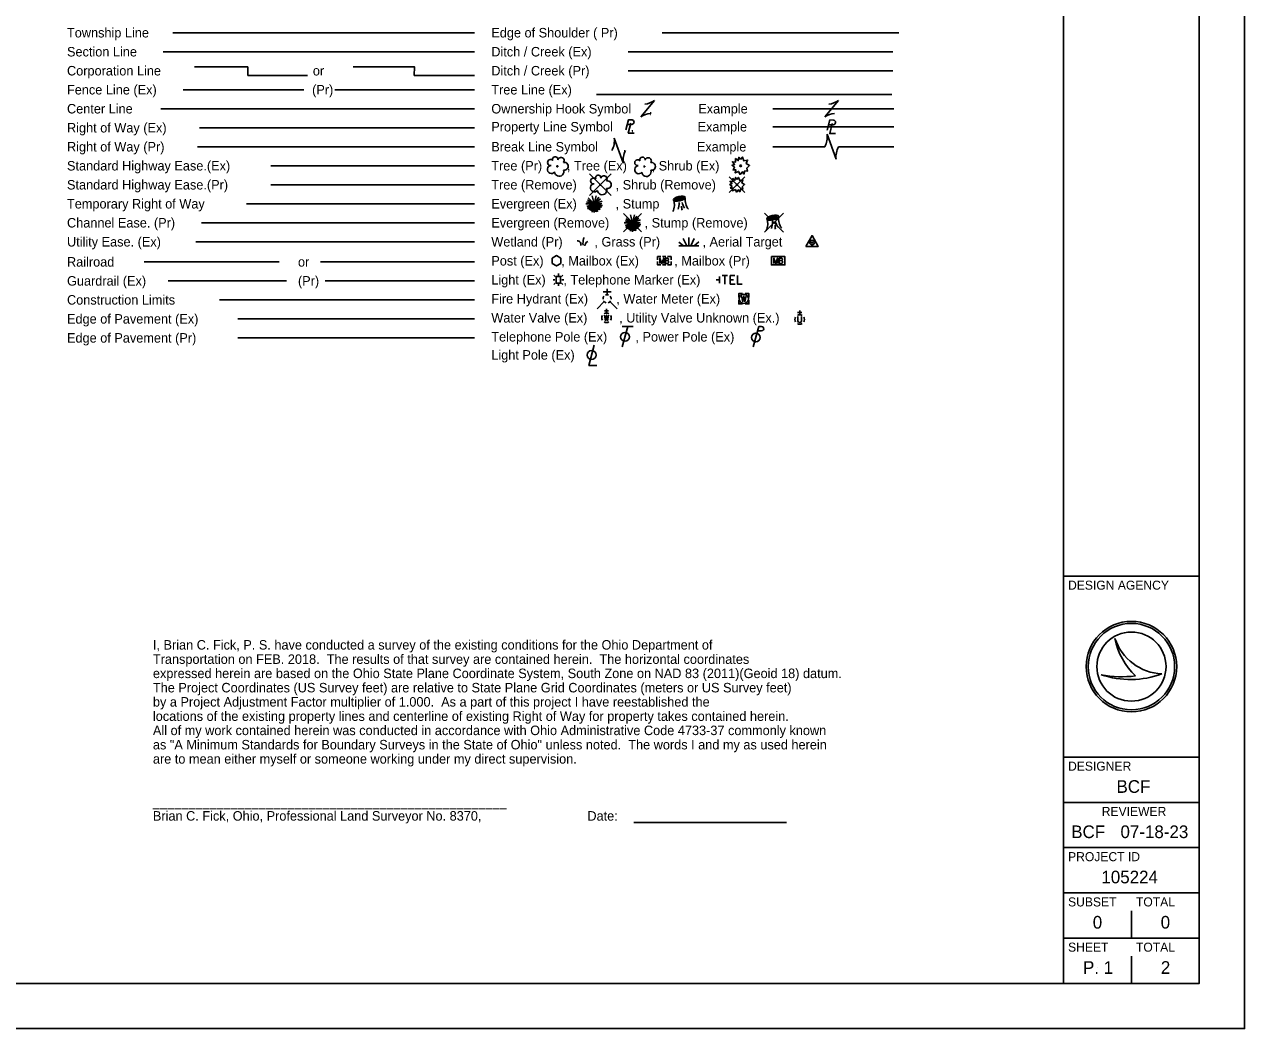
# Model space of a CAD drawing. Extents: x 0 to 1052, y -194 to 246.
# Drawn here: x 20.52 to 34, y 0 to 11.1 of the extents above; entities that cross this region are included whole.
import ezdxf

# ---------------------------------------------------------------- set-up
doc = ezdxf.new("R2010")
doc.units = 0
for name, color, linetype in [('SH_Border', 7, 'Continuous'), ('SH_Cut_Line', 7, 'Continuous'), ('SH_Data', 7, 'Continuous'), ('SH_Text', 7, 'Continuous')]:
    doc.layers.add(name, color=color, linetype=linetype)

msp = doc.modelspace()

# ---------------------------------------------------------------- linework, layer by layer
at = {"layer": 'SH_Border'}
for p, q in [((32, 0.5), (32, 21.5)), ((32, 5), (33.5, 5)), ((32, 3), (33.5, 3)), ((32, 2.5), (33.5, 2.5)), ((32, 2), (33.5, 2)), ((32, 1.5), (33.5, 1.5)), ((32, 1), (33.5, 1))]:
    msp.add_line(p, q, dxfattribs=at)
msp.add_lwpolyline([(1.5, 21.5), (33.5, 21.5), (33.5, 0.5), (1.5, 0.5)], close=True, dxfattribs=at)
at = {"layer": 'SH_Cut_Line'}
msp.add_lwpolyline([(0, 0), (34, 0), (34, 22), (0, 22)], close=True, dxfattribs=at)
at = {"layer": 'SH_Data'}
for p, q in [((32.567, 4.31), (32.567, 4.31)), ((32.417, 3.91), (32.417, 3.91)), ((32.75, 4), (32.75, 4)), ((33.087, 3.919), (33.087, 3.919)), ((32.75, 1), (32.75, 1.3)), ((32.375, 0.675), (32.375, 0.675)), ((32.75, 0.5), (32.75, 0.8))]:
    msp.add_line(p, q, dxfattribs=at)
for radius in [0.5, 0.477, 0.477, 0.382]:
    msp.add_circle((32.75, 4), radius, dxfattribs=at)
for centre, radius, start, end in [((33.116, 4.498), 0.58, 198.9257, 198.9319), ((33.347, 4.47), 0.796, 191.6379, 191.6421), ((33.116, 4.498), 0.58, 198.9319, 267.1657), ((33.347, 4.47), 0.796, 191.6421, 226.0947), ((32.739, 4.87), 1.013, 251.4576, 290.0832), ((32.648, 5.154), 1.266, 259.4964, 259.4995), ((32.739, 4.87), 1.013, 251.4527, 251.4576), ((32.648, 5.154), 1.266, 259.4995, 276.6672)]:
    msp.add_arc(centre, radius, start, end, dxfattribs=at)
at = {"layer": 'SH_Text'}
for p, q in [((22.161, 11.004), (25.492, 11.004)), ((27.567, 11.004), (30.179, 11.004)), ((22.054, 10.794), (25.492, 10.794)), ((27.191, 10.794), (30.116, 10.794)), ((22.402, 10.627), (22.989, 10.627)), ((22.989, 10.627), (22.989, 10.532)), ((22.989, 10.532), (23.65, 10.532)), ((27.191, 10.584), (30.116, 10.584)), ((22.277, 10.374), (23.607, 10.374)), ((23.949, 10.374), (25.492, 10.374)), ((26.841, 10.322), (30.103, 10.322)), ((27.332, 10.074), (27.482, 10.254)), ((29.363, 10.074), (29.513, 10.254)), ((22.028, 10.164), (25.492, 10.164)), ((27.407, 10.164), (27.407, 10.164)), ((28.789, 10.164), (30.126, 10.164)), ((29.438, 10.164), (29.438, 10.164)), ((27.182, 9.991), (27.231, 9.991)), ((29.406, 9.988), (29.455, 9.988)), ((22.454, 9.954), (25.492, 9.954)), ((27.037, 9.841), (27.135, 9.565)), ((27.212, 9.968), (27.212, 9.968)), ((28.789, 9.966), (30.126, 9.966)), ((29.389, 9.883), (29.487, 9.606)), ((29.436, 9.965), (29.436, 9.965)), ((22.433, 9.744), (25.492, 9.744)), ((28.789, 9.744), (29.363, 9.744)), ((29.438, 9.744), (29.438, 9.744)), ((29.513, 9.744), (30.126, 9.744)), ((27.086, 9.703), (27.086, 9.703)), ((23.242, 9.534), (25.492, 9.534)), ((26.762, 9.445), (27.003, 9.204)), ((27.003, 9.445), (26.762, 9.204)), ((23.242, 9.324), (25.492, 9.324)), ((26.882, 9.324), (26.882, 9.324)), ((28.306, 9.411), (28.48, 9.237)), ((28.48, 9.411), (28.306, 9.237)), ((28.393, 9.324), (28.393, 9.324)), ((26.815, 9.114), (26.75, 9.18)), ((26.815, 9.114), (26.792, 9.201)), ((26.815, 9.114), (26.839, 9.202)), ((26.815, 9.114), (26.865, 9.187)), ((26.815, 9.114), (26.884, 9.167)), ((22.976, 9.114), (25.492, 9.114)), ((26.723, 9.114), (26.815, 9.114)), ((26.815, 9.114), (26.732, 9.136)), ((26.815, 9.114), (26.735, 9.085)), ((26.815, 9.114), (26.741, 9.071)), ((26.815, 9.114), (26.742, 9.157)), ((26.815, 9.114), (26.742, 9.058)), ((26.815, 9.114), (26.76, 9.049)), ((26.815, 9.114), (26.772, 9.039)), ((26.815, 9.114), (26.784, 9.033)), ((26.815, 9.114), (26.792, 9.023)), ((26.815, 9.114), (26.805, 9.028)), ((26.815, 9.114), (26.904, 9.144)), ((26.815, 9.114), (26.9, 9.116)), ((26.815, 9.016), (26.815, 9.114)), ((26.815, 9.114), (26.833, 9.027)), ((26.815, 9.114), (26.851, 9.027)), ((26.815, 9.114), (26.863, 9.043)), ((26.815, 9.114), (26.883, 9.048)), ((26.815, 9.114), (26.887, 9.066)), ((26.815, 9.114), (26.899, 9.078)), ((26.815, 9.114), (26.906, 9.096)), ((27.77, 9.114), (27.77, 9.114)), ((22.479, 8.904), (25.492, 8.904)), ((27.138, 9.005), (27.339, 8.804)), ((27.339, 9.005), (27.138, 8.804)), ((27.146, 8.904), (27.238, 8.904)), ((27.238, 8.904), (27.156, 8.927)), ((27.238, 8.904), (27.158, 8.875)), ((27.238, 8.904), (27.164, 8.862)), ((27.238, 8.904), (27.165, 8.947)), ((27.238, 8.904), (27.165, 8.848)), ((27.238, 8.904), (27.173, 8.97)), ((27.238, 8.904), (27.183, 8.839)), ((27.238, 8.904), (27.195, 8.829)), ((27.238, 8.904), (27.207, 8.823)), ((27.238, 8.904), (27.215, 8.991)), ((27.238, 8.904), (27.215, 8.813)), ((27.238, 8.904), (27.228, 8.818)), ((27.238, 8.904), (27.262, 8.992)), ((27.238, 8.904), (27.288, 8.977)), ((27.238, 8.904), (27.307, 8.957)), ((27.238, 8.904), (27.327, 8.935)), ((27.238, 8.904), (27.323, 8.906)), ((27.238, 8.806), (27.238, 8.904)), ((27.238, 8.904), (27.256, 8.817)), ((27.238, 8.904), (27.275, 8.817)), ((27.238, 8.904), (27.286, 8.833)), ((27.238, 8.904), (27.306, 8.838)), ((27.238, 8.904), (27.31, 8.856)), ((27.238, 8.904), (27.322, 8.868)), ((27.238, 8.904), (27.329, 8.886)), ((27.238, 8.904), (27.238, 8.904)), ((28.698, 9.009), (28.906, 8.8)), ((28.906, 9.009), (28.698, 8.8)), ((28.802, 8.904), (28.802, 8.904)), ((28.802, 8.904), (28.802, 8.904)), ((22.416, 8.694), (25.492, 8.694)), ((27.803, 8.649), (27.752, 8.691)), ((27.752, 8.648), (27.972, 8.651)), ((27.839, 8.649), (27.8, 8.729)), ((27.862, 8.649), (27.861, 8.743)), ((27.884, 8.65), (27.921, 8.73)), ((27.921, 8.65), (27.971, 8.695)), ((27.57, 8.53), (27.608, 8.53)), ((21.845, 8.473), (23.335, 8.473)), ((23.792, 8.473), (25.492, 8.473)), ((27.57, 8.439), (27.608, 8.439)), ((27.59, 8.484), (27.59, 8.484)), ((28.848, 8.484), (28.848, 8.484)), ((22.111, 8.263), (23.418, 8.263)), ((23.845, 8.263), (25.492, 8.263)), ((26.381, 8.275), (26.361, 8.275)), ((26.384, 8.311), (26.37, 8.325)), ((26.384, 8.238), (26.37, 8.224)), ((26.42, 8.322), (26.42, 8.342)), ((26.42, 8.274), (26.42, 8.274)), ((26.42, 8.226), (26.42, 8.206)), ((26.47, 8.325), (26.456, 8.311)), ((26.47, 8.224), (26.456, 8.238)), ((26.479, 8.275), (26.459, 8.275)), ((28.199, 8.274), (28.162, 8.274)), ((28.199, 8.237), (28.199, 8.312)), ((27.003, 8.142), (26.913, 8.142)), ((26.958, 8.11), (26.958, 8.174)), ((22.675, 8.053), (25.492, 8.053)), ((26.927, 8.033), (26.849, 7.955)), ((26.952, 7.907), (26.952, 7.955)), ((26.958, 8.064), (26.958, 8.064)), ((26.958, 8.064), (26.958, 8.064)), ((26.99, 8.033), (27.068, 7.955)), ((28.469, 8.064), (28.469, 8.064)), ((22.879, 7.843), (25.492, 7.843)), ((26.975, 7.931), (26.928, 7.931)), ((26.952, 7.854), (26.952, 7.854)), ((29.11, 7.911), (29.062, 7.911)), ((29.066, 7.867), (29.066, 7.815)), ((29.086, 7.887), (29.086, 7.935)), ((29.086, 7.835), (29.086, 7.835)), ((29.106, 7.867), (29.106, 7.815)), ((27.246, 7.757), (27.126, 7.757)), ((27.186, 7.757), (27.126, 7.532)), ((28.633, 7.757), (28.573, 7.532)), ((28.62, 7.709), (28.665, 7.709)), ((28.633, 7.757), (28.665, 7.757)), ((22.879, 7.633), (25.492, 7.633)), ((27.255, 2.278), (28.941, 2.278))]:
    msp.add_line(p, q, dxfattribs=at)
for points in [[(24.154, 10.627), (24.832, 10.627), (24.827, 10.532), (25.492, 10.532)], [(27.166, 9.931), (27.196, 10.043), (27.234, 10.043)], [(27.222, 10.004), (27.192, 9.893), (27.258, 9.893)], [(29.39, 9.928), (29.42, 10.04), (29.459, 10.039)], [(29.446, 10.001), (29.417, 9.89), (29.482, 9.89)], [(28.43, 9.602), (28.453, 9.63), (28.468, 9.59), (28.509, 9.597), (28.496, 9.559), (28.532, 9.537), (28.5, 9.509), (28.509, 9.475), (28.481, 9.478), (28.469, 9.443), (28.453, 9.469), (28.427, 9.439), (28.411, 9.472), (28.373, 9.456), (28.38, 9.491), (28.35, 9.488), (28.367, 9.518), (28.339, 9.539), (28.366, 9.549), (28.343, 9.579), (28.378, 9.575), (28.377, 9.614), (28.406, 9.592), (28.413, 9.629), (28.43, 9.602)], [(28.391, 9.382), (28.41, 9.405), (28.423, 9.372), (28.458, 9.378), (28.447, 9.345), (28.477, 9.326), (28.45, 9.303), (28.458, 9.274), (28.434, 9.276), (28.424, 9.247), (28.41, 9.269), (28.388, 9.243), (28.375, 9.271), (28.342, 9.258), (28.348, 9.288), (28.322, 9.285), (28.337, 9.31), (28.313, 9.328), (28.337, 9.337), (28.317, 9.362), (28.347, 9.359), (28.346, 9.392), (28.37, 9.374), (28.377, 9.405), (28.391, 9.382)], [(26.35, 8.456), (26.399, 8.428), (26.447, 8.456), (26.447, 8.513), (26.399, 8.541), (26.35, 8.513), (26.35, 8.456)], [(27.515, 8.494), (27.515, 8.53), (27.551, 8.53)], [(27.541, 8.454), (27.541, 8.514), (27.563, 8.454), (27.583, 8.514), (27.583, 8.454)], [(27.628, 8.487), (27.63, 8.489), (27.632, 8.491), (27.633, 8.492), (27.633, 8.493), (27.634, 8.495), (27.634, 8.496), (27.635, 8.5), (27.635, 8.501), (27.635, 8.503), (27.635, 8.506), (27.634, 8.508), (27.633, 8.51), (27.63, 8.512), (27.628, 8.513), (27.627, 8.513), (27.625, 8.514), (27.602, 8.514), (27.602, 8.454), (27.628, 8.454), (27.631, 8.456), (27.634, 8.459), (27.636, 8.462), (27.638, 8.467), (27.638, 8.471), (27.638, 8.474), (27.637, 8.477), (27.635, 8.481), (27.633, 8.484), (27.628, 8.487), (27.602, 8.487)], [(27.627, 8.53), (27.665, 8.53), (27.665, 8.494)], [(28.8, 8.454), (28.8, 8.514), (28.821, 8.454), (28.842, 8.514), (28.842, 8.454)], [(28.886, 8.487), (28.889, 8.489), (28.89, 8.491), (28.891, 8.492), (28.892, 8.493), (28.893, 8.495), (28.893, 8.496), (28.894, 8.5), (28.894, 8.501), (28.894, 8.503), (28.894, 8.506), (28.893, 8.508), (28.891, 8.51), (28.889, 8.512), (28.887, 8.513), (28.886, 8.513), (28.884, 8.514), (28.86, 8.514), (28.86, 8.454), (28.886, 8.454), (28.89, 8.456), (28.893, 8.459), (28.895, 8.462), (28.896, 8.467), (28.897, 8.471), (28.897, 8.474), (28.896, 8.477), (28.894, 8.481), (28.892, 8.484), (28.886, 8.487), (28.86, 8.487)], [(27.551, 8.439), (27.515, 8.439), (27.515, 8.475)], [(27.665, 8.475), (27.665, 8.439), (27.627, 8.439)], [(28.23, 8.321), (28.288, 8.321)], [(28.259, 8.321), (28.259, 8.227)], [(28.369, 8.321), (28.318, 8.321), (28.318, 8.227), (28.372, 8.227)], [(28.318, 8.274), (28.354, 8.274)], [(28.398, 8.321), (28.398, 8.227), (28.449, 8.227)], [(28.454, 8.121), (28.412, 8.121), (28.412, 8.079)], [(28.444, 8.098), (28.456, 8.031), (28.469, 8.098), (28.481, 8.031), (28.494, 8.098)], [(28.525, 8.079), (28.525, 8.121), (28.484, 8.121)], [(28.412, 8.049), (28.412, 8.008), (28.454, 8.008)], [(28.484, 8.008), (28.525, 8.008), (28.525, 8.049)], [(26.928, 7.885), (26.94, 7.821), (26.952, 7.885), (26.964, 7.821), (26.975, 7.885)], [(26.817, 7.553), (26.758, 7.329), (26.846, 7.329)]]:
    msp.add_lwpolyline(points, dxfattribs=at)
for points in [[(29.154, 8.642), (29.289, 8.642), (29.222, 8.763)], [(28.773, 8.53), (28.923, 8.53), (28.923, 8.439), (28.773, 8.439)], [(26.395, 8.237), (26.445, 8.237), (26.445, 8.312), (26.395, 8.312)]]:
    msp.add_lwpolyline(points, close=True, dxfattribs=at)
for centre, radius in [((26.408, 9.528), 0.0063), ((27.371, 9.526), 0.0054), ((28.433, 9.534), 0.00864), ((26.882, 9.324), 0.0054), ((28.393, 9.324), 0.00734), ((29.222, 8.685), 0.0263), ((29.222, 8.685), 0.006), ((28.469, 8.064), 0.0506), ((27.156, 7.644), 0.0488), ((28.601, 7.637), 0.0488), ((26.787, 7.443), 0.0488)]:
    msp.add_circle(centre, radius, dxfattribs=at)
for centre, radius, start, end in [((27.363, 10.416), 0.2, 273.6945, 306.337), ((29.394, 10.416), 0.2, 273.6945, 306.337), ((27.45, 9.913), 0.2, 93.6945, 126.337), ((29.482, 9.913), 0.2, 93.6945, 126.337), ((27.23, 10.017), 0.0259, 270.471, 81.3281), ((29.455, 10.014), 0.0259, 270.471, 81.3281), ((26.789, 9.816), 0.25, 332.9422, 5.5848), ((29.14, 9.858), 0.25, 332.9422, 5.5848), ((29.736, 9.631), 0.25, 152.9422, 185.5848), ((26.333, 9.57), 0.0331, 39.0625, 279.5412), ((26.385, 9.604), 0.0296, 354.0047, 205.9741), ((26.449, 9.592), 0.0349, 323.83, 165.0376), ((26.485, 9.529), 0.0431, 259.1453, 101.4596), ((27.384, 9.589), 0.25, 152.9422, 185.5848), ((27.297, 9.568), 0.0331, 39.0625, 279.5412), ((27.349, 9.601), 0.0296, 354.0047, 205.9741), ((27.412, 9.589), 0.0349, 323.83, 165.0376), ((26.343, 9.493), 0.0444, 96.1722, 320.5737), ((26.429, 9.47), 0.0514, 184.9476, 19.4572), ((27.307, 9.491), 0.0444, 96.1722, 320.5737), ((27.392, 9.467), 0.0514, 184.9476, 19.4572), ((27.449, 9.527), 0.0431, 259.1453, 101.4596), ((26.818, 9.29), 0.0444, 96.1722, 320.5737), ((26.808, 9.366), 0.0331, 39.0625, 279.5412), ((26.86, 9.4), 0.0296, 354.0047, 205.9741), ((26.923, 9.388), 0.0349, 323.83, 165.0376), ((26.96, 9.325), 0.0431, 259.1453, 101.4596), ((26.904, 9.266), 0.0514, 184.9476, 19.4572), ((27.981, 9.157), 0.161, 171.4106, 219.9194), ((27.552, 9.101), 0.15, 331.5338, 20.9269), ((27.564, 9.115), 0.189, 340.7938, 3.5481), ((27.917, 9.084), 0.136, 178.7926, 197.1224), ((28.015, 9.191), 0.237, 194.9653, 212.1216), ((28.583, 8.891), 0.15, 331.5338, 20.9269), ((28.595, 8.905), 0.189, 340.7938, 3.5481), ((29.046, 8.981), 0.237, 194.9653, 212.1216), ((29.012, 8.947), 0.161, 171.4106, 219.9194), ((28.949, 8.874), 0.136, 178.7926, 197.1224), ((26.958, 8.064), 0.045, 140.021, 184.0629), ((26.958, 8.064), 0.045, 68.1395, 112.038), ((26.958, 8.064), 0.045, 356.0165, 39.9889), ((26.958, 8.064), 0.045, 211.8788, 255.8479), ((26.958, 8.064), 0.045, 283.8239, 329.9097), ((26.951, 7.854), 0.0525, 150.0184, 209.9816), ((26.951, 7.854), 0.0525, 60.0184, 120.0157), ((26.951, 7.854), 0.0525, 330.0184, 29.9816), ((29.086, 7.835), 0.0525, 150.0184, 209.9816), ((29.086, 7.835), 0.0525, 60.0184, 120.0157), ((29.086, 7.835), 0.0525, 330.0184, 29.9816), ((26.951, 7.854), 0.0525, 239.9843, 299.9816), ((28.665, 7.733), 0.0239, 268.8767, 91.1233), ((29.086, 7.835), 0.0525, 239.9843, 299.9816), ((29.086, 7.825), 0.0225, 205.1924, 334.8076)]:
    msp.add_arc(centre, radius, start, end, dxfattribs=at)
for centre, major_axis in [((27.756, 9.171), (0.0651, 0.0141)), ((27.756, 9.171), (0.0488, 0.0105)), ((27.756, 9.171), (0.0366, 0.0079)), ((27.756, 9.171), (0.0206, 0.0044)), ((27.756, 9.171), (0.0116, 0.0025)), ((28.788, 8.961), (0.0651, 0.0141)), ((28.788, 8.961), (0.0488, 0.0105)), ((28.788, 8.961), (0.0366, 0.0079)), ((28.788, 8.961), (0.0206, 0.0044)), ((28.788, 8.961), (0.0116, 0.0025))]:
    msp.add_ellipse(centre, major_axis=major_axis, ratio=0.36865, dxfattribs=at)
for points in [[(26.627, 8.706), (26.658, 8.693), (26.671, 8.653)], [(26.692, 8.656), (26.692, 8.691), (26.697, 8.725), (26.703, 8.74)], [(26.713, 8.65), (26.722, 8.679), (26.744, 8.697)]]:
    msp.add_spline(points, degree=3, dxfattribs=at)

# ---------------------------------------------------------------- texts
at = {"layer": 'SH_Data'}
for s, height, p in [('DESIGN AGENCY', 0.1, (32.05, 4.85)), ('DESIGNER', 0.1, (32.05, 2.85)), ('BCF', 0.14, (32.585, 2.605)), ('REVIEWER', 0.1, (32.422, 2.35)), ('BCF', 0.14, (32.085, 2.105)), ('07-18-23', 0.14, (32.629, 2.105)), ('PROJECT ID', 0.1, (32.05, 1.85)), ('105224', 0.14, (32.418, 1.605)), ('SUBSET', 0.1, (32.05, 1.35)), ('TOTAL', 0.1, (32.8, 1.35)), ('0', 0.14, (32.323, 1.105)), ('0', 0.14, (33.073, 1.105)), ('SHEET', 0.1, (32.05, 0.85)), ('TOTAL', 0.1, (32.8, 0.85)), ('P. 1', 0.14, (32.215, 0.605)), ('2', 0.14, (33.075, 0.605))]:
    msp.add_text(s, height=height, dxfattribs=at).set_placement(p)
at = {"layer": 'SH_Text'}
for s, p in [('Township Line', (20.992, 10.952)), ('Edge of Shoulder ( Pr)', (25.679, 10.952)), ('Section Line', (20.992, 10.742)), ('Ditch / Creek (Ex)', (25.679, 10.742)), ('Corporation Line                                           or', (20.992, 10.532)), ('Ditch / Creek (Pr)', (25.679, 10.532)), ('Fence Line (Ex)                                            (Pr)', (20.992, 10.322)), ('Tree Line (Ex)', (25.679, 10.322)), ('Center Line', (20.992, 10.112)), ('Ownership Hook Symbol     ,             Example', (25.679, 10.112)), ('Right of Way (Ex)', (20.992, 9.902)), ('Property Line Symbol     ,                  Example', (25.679, 9.913)), ('Right of Way (Pr)', (20.992, 9.692)), ('Break Line Symbol       ,                    Example', (25.679, 9.692)), ('Standard Highway Ease.(Ex)', (20.992, 9.482)), ('Tree (Pr)       , Tree (Ex)       , Shrub (Ex)', (25.679, 9.482)), ('Standard Highway Ease.(Pr)', (20.992, 9.272)), ('Tree (Remove)           , Shrub (Remove)', (25.679, 9.272)), ('Temporary Right of Way', (20.992, 9.062)), ('Evergreen (Ex)           , Stump ', (25.679, 9.062)), ('Channel Ease. (Pr)', (20.992, 8.852)), ('Evergreen (Remove)          , Stump (Remove)', (25.679, 8.852)), ('Utility Ease. (Ex)', (20.992, 8.642)), ('Wetland (Pr)         , Grass (Pr)            , Aerial Target    ', (25.679, 8.642)), ('Railroad                                                    or', (20.992, 8.42)), ('Post (Ex)     , Mailbox (Ex)          , Mailbox (Pr)', (25.679, 8.432)), ('Guardrail (Ex)                                           (Pr)', (20.992, 8.21)), ('Light (Ex)     , Telephone Marker (Ex)     ', (25.679, 8.222)), ('Construction Limits', (20.992, 8)), ('Fire Hydrant (Ex)        , Water Meter (Ex)', (25.679, 8.012)), ('Edge of Pavement (Ex)', (20.992, 7.79)), ('Water Valve (Ex)         , Utility Valve Unknown (Ex.)', (25.679, 7.802)), ('Edge of Pavement (Pr)', (20.992, 7.58)), ('Telephone Pole (Ex)        , Power Pole (Ex)', (25.679, 7.592)), ('Light Pole (Ex)     ', (25.679, 7.392)), ('I, Brian C. Fick, P. S. have conducted a survey of the existing conditions for the Ohio Department of', (21.941, 4.188)), ('Transportation on FEB. 2018.  The results of that survey are contained herein.  The horizontal coordinates', (21.941, 4.03)), ('expressed herein are based on the Ohio State Plane Coordinate System, South Zone on NAD 83 (2011)(Geoid 18) datum.', (21.941, 3.873)), ('The Project Coordinates (US Survey feet) are relative to State Plane Grid Coordinates (meters or US Survey feet)', (21.941, 3.715)), ('by a Project Adjustment Factor multiplier of 1.000.  As a part of this project I have reestablished the', (21.941, 3.558)), ('locations of the existing property lines and centerline of existing Right of Way for property takes contained herein.  ', (21.941, 3.4)), ('All of my work contained herein was conducted in accordance with Ohio Administrative Code 4733-37 commonly known', (21.941, 3.243)), ('as "A Minimum Standards for Boundary Surveys in the State of Ohio" unless noted.  The words I and my as used herein', (21.941, 3.085)), ('are to mean either myself or someone working under my direct supervision.', (21.941, 2.928)), ('__________________________________________________', (21.941, 2.455)), ('Brian C. Fick, Ohio, Professional Land Surveyor No. 8370,                              Date: ', (21.941, 2.298))]:
    msp.add_text(s, height=0.105, dxfattribs=at).set_placement(p)

doc.saveas('drawing.dxf')
